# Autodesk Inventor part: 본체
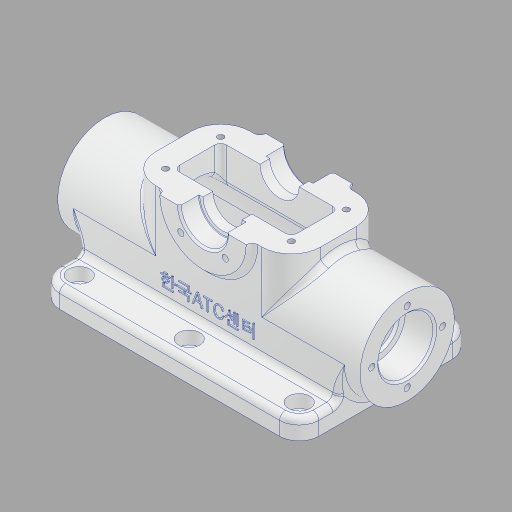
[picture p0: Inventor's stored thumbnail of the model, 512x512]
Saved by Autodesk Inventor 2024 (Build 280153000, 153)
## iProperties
Created: 2024-06
Part Number: 본체
Material: 알루미늄 6061
Document SubType Name: Modeling
Designer: kh_501
Density: 2.7 g/cm^3
Appearance: 알루미늄 - 평지
Mass: 551.84 g
Surface Area: 612.281 cm^2
Volume: 204.385 cm^3
Author: kh_501
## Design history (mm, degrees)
sketch "스케치1"
  geometry: L1 (66, 44)-(-66, 44); L2 (-66, 44)-(-66, -44); L3 (-66, -44)-(66, -44); L4 (66, -44)-(66, 44); L5 (66, 44)-(-66, -44); L6 (-66, 44)-(66, -44); 1 further point
  constraints: 12 end point, 2 midpoint, 2 parallel, 1 horizontal, 1 perpendicular
  dimensions: "d0" = 132 distance of L1.start L1.end; "d1" = 88 distance of L1.end L2.end
extrude "돌출1" new body sketch "스케치1" distance "d2" = 10; taper "d3" = 0 deg
sketch "스케치2"
  geometry: L1 (-77, 52)-(77, 52); L2 (77, 52)-(77, 28); L3 (77, 28)-(-77, 28); L4 (-77, 28)-(-77, 52); L5 (66, 0)-(-66, 0) reference; 2 further points
  constraints: 8 end point, 2 parallel, 1 horizontal, 1 midpoint, 1 perpendicular, 1 vertical alignment
  dimensions: "d4" = 48 diameter of L1 L3; "d5" = 28 distance from line of L5 L3.end; "d6" = 154 distance of L1.end L1.start
revolve "회전1" sketch "스케치2" stored, may be unused: angle "d7" = 90 deg
node "작업 평면1"
sketch "스케치4"
  geometry: L1 (-42, 24)-(42, 24); L2 (42, 24)-(42, -24); L3 (42, -24)-(-42, -24); L4 (-42, -24)-(-42, 24); L5 (-42, 24)-(42, -24); L6 (42, 24)-(-42, -24); 1 further point
  constraints: 12 end point, 2 midpoint, 2 parallel, 1 horizontal, 1 perpendicular
  dimensions: "d9" = 84 distance of L2.end L3.end; "d10" = 48 distance of L3.end L1.start
extrude "돌출2" join sketch "스케치4" stored distance "d11" = 10; taper "d12" = 0 deg
sketch "스케치8"
  geometry: L1 (84, -31)-(0, -31) reference; L2 (-24, -59)-(108, -59) reference; L3 (0, 0)-(84, 0) reference; C1 r 22 at (42, 0); 4 further points
  constraints: 1 centre point, 1 midpoint, 1 vertical alignment
  dimensions: "d19" = 44 diameter of C1; "d20" = 59 distance from line of L2 C1.centre
extrude "돌출4" join sketch "스케치8" distance "d21" = 3; taper "d22" = 0 deg
sketch "스케치9"
  geometry: L1 (88, 10)-(59.875, 10) reference; L2 (88, 0)-(88, 10) reference; L3 (88, 0)-(0, 0) reference; L4 (0, 0)-(0, 10) reference; L5 (28.125, 10)-(0, 10) reference; L6 (20, 28)-(20, 9.172); L7 (68, 28)-(68, 9.172); A1 r 24 centre (44, 28) between (28.125, 10) and (59.875, 10) reference; A2 r 24 centre (44, 28) between (20, 28) and (68, 28) reference; 5 further points
  constraints: 4 end point, 2 point on circle, 2 tangent, 2 vertical
extrude "돌출5" join sketch "스케치9" distance "d23" = 132; taper "d24" = 0 deg
sketch "스케치5"
  geometry: L1 (28, 0)-(-63.528, 0); L2 (28, -18)-(-63.528, -18); L3 (-63.528, 18)-(28, 18); L4 (0, 44)-(0, -44) reference; C1 r 24 at (28, 0) reference; A1 r 18 centre (28, 0) between (28, -18) and (28, 18); A2 r 18 centre (-63.528, 0) between (-63.528, 18) and (-63.528, -18); 5 further points
  constraints: 8 end point, 4 point on circle, 4 tangent, 2 centre point, 2 midpoint, 1 horizontal, 1 horizontal alignment, 1 parallel
  dimensions: "d15" = 28 distance from line of L4 L1.start; "d16" = 6 radial gap between concentric circles of C1 A1
extrude "돌출3" cut sketch "스케치5" stored distance "d17" = 120; taper "d18" = 0 deg
sketch "스케치10"
  geometry: L1 (-30, -12)-(30, -12); L2 (30, -12)-(30, 12); L3 (30, 12)-(-30, 12); L4 (-30, 12)-(-30, -12); L5 (-30, -12)-(30, 12); L6 (30, -12)-(-30, 12); 1 further point
  constraints: 12 end point, 2 midpoint, 2 parallel, 1 horizontal, 1 perpendicular
  dimensions: "d25" = 60 distance of L2.end L3.end; "d26" = 24 distance of L1.end L2.end
extrude "돌출6" cut sketch "스케치10" stored distance "d27" = 132; taper "d28" = 0 deg
sketch "스케치11"
  geometry: A1 r 22 centre (42, 0) between (20, 0) and (64, 0) reference; 2 further points
  constraints: 1 coincident
hole "구멍1" sketch "스케치11" at (42, 0) diameter "d29" = 20; stored, may be unused: countersink angle "d33" = 90 deg, drill point angle "d35" = 0 deg; dims "d30" = 6, "d31" = 24, "d32" = 10, "d34" = 8
sketch "스케치12"
  geometry: A1 r 22 centre (0, 0) between (-22, 0) and (22, 0) reference; 2 further points
  constraints: 1 coincident
hole "구멍2" sketch "스케치12" at (0, 0) diameter "d36" = 20; stored, may be unused: countersink angle "d40" = 90 deg, drill point angle "d42" = 0 deg; dims "d37" = 6, "d38" = 24, "d39" = 10, "d41" = 8
sketch "스케치13"
  geometry: C1 r 24 at (0, 0) reference; 2 further points
  constraints: 1 coincident
hole "구멍3" sketch "스케치13" at (0, 0) diameter "d43" = 22; stored, may be unused: countersink angle "d47" = 90 deg, drill point angle "d49" = 0 deg; dims "d44" = 6, "d45" = 28, "d46" = 15, "d48" = 8
sketch "스케치14"
  geometry: C1 r 24 at (0, 0) reference; 2 further points
  constraints: 1 coincident
hole "구멍4" sketch "스케치14" at (0, 0) diameter "d50" = 22; stored, may be unused: countersink angle "d54" = 90 deg, drill point angle "d56" = 0 deg; dims "d51" = 6, "d52" = 28, "d53" = 15, "d55" = 8
sketch "스케치15" dims "d57" = 36
  geometry: L1 (0, 0)-(0, 18); C1 r 14 at (0, 0) reference; C2 r 24 at (0, 0) reference; 2 further points
  constraints: 2 coincident, 2 end point, 1 vertical, 1 vertical alignment, 2 other
hole "구멍5" sketch "스케치15" at (0, 18) diameter "d58" = 3.242; stored, may be unused: countersink angle "d62" = 90 deg, drill point angle "d64" = 118 deg; dims "d59" = 8, "d60" = 28, "d61" = 15, "d63" = 10
sketch "스케치16"
  geometry: L1 (-32, -14)-(32, -14); L2 (32, -14)-(32, 14); L3 (32, 14)-(-32, 14); L4 (-32, 14)-(-32, -14); L5 (-32, -14)-(32, 14); L6 (32, -14)-(-32, 14); 5 further points
  constraints: 12 end point, 4 coincident, 2 midpoint, 2 parallel, 1 horizontal, 1 perpendicular
  dimensions: "d68" = 64 distance of L2.end L3.end; "d69" = 28 distance of L1.end L2.end
hole "구멍6" sketch "스케치16" at (-32, 14), (-32, -14), (32, -14), (32, 14) diameter "d70" = 3.242; stored, may be unused: countersink angle "d74" = 90 deg, drill point angle "d76" = 118 deg; dims "d71" = 8, "d72" = 4, "d73" = 2, "d75" = 10
sketch "스케치17" dims "d77" = 32
  geometry: L1 (42, 0)-(30.686, -11.314); L2 (42, 0)-(42, 13.322); A1 r 12 centre (42, 0) between (30, 0) and (54, 0) reference; 2 further points
  constraints: 4 end point, 2 coincident, 1 vertical, 3 other
  dimensions: "d78" = 45 deg angle of L1 L2
hole "구멍7" sketch "스케치17" at (30.686, -11.314) diameter "d79" = 3.242; stored, may be unused: countersink angle "d83" = 90 deg, drill point angle "d85" = 118 deg; dims "d80" = 8, "d81" = 4, "d82" = 2, "d84" = 10
fillet "모깎기1" dims "d89" = 10
sketch "스케치18"
  geometry: L1 (-56, -34)-(56, -34); L2 (56, -34)-(56, 34); L3 (56, 34)-(-56, 34); L4 (-56, 34)-(-56, -34); L5 (-56, -34)-(56, 34); L6 (56, -34)-(-56, 34); 7 further points
  constraints: 12 end point, 4 coincident, 4 midpoint, 2 parallel, 1 horizontal, 1 perpendicular
  dimensions: "d90" = 112 distance of L2.end L3.end; "d91" = 68 distance of L1.end L2.end
hole "구멍8" sketch "스케치18" at (-56, 34), (-56, -34), (0, -34), (0, 34), (56, 34), (56, -34) diameter "d92" = 6.6; stored, may be unused: countersink angle "d96" = 90 deg, drill point angle "d98" = 118 deg; dims "d93" = 8, "d94" = 11, "d95" = 6.6, "d97" = 10
sketch "스케치19"
  geometry: L1 (10, -10)-(122, -10) reference; 3 further points
  constraints: 1 midpoint, 1 vertical alignment, 1 other
  dimensions: "d99" = 20 distance from line of L1 point (66, 10)
feature "엠보싱1" sketch "스케치19" dims "d100" = 0.5, "d101" = 0
fillet "모깎기2" dims "d102" = 3
fillet "모깎기3" dims "d103" = 3
fillet "모깎기4" dims "d104" = 3
fillet "모깎기5" dims "d105" = 15
fillet "모깎기6" dims "d106" = 3
fillet "모깎기7" dims "d107" = 3
fillet "모깎기8" dims "d108" = 3
chamfer "모따기1" distance "d109" = 1; stored, may be unused: second distance "d110" = 2, angle "d111" = 45 deg
fillet "모깎기9" dims "d112" = 3
fillet "모깎기10" dims "d113" = 0.3
node "솔리드1"
mirror "미러1"
pattern_circular "원형 패턴1" dims angle "d66" = 360 deg
mirror "미러2"
pattern_circular "원형 패턴2" dims angle "d87" = 90 deg
mirror "미러3"
node "투영된 루프2"
node "투영된 루프3"
node "투영된 루프4"
feature "A9D066F2-1C7D-4E18-AEED-F7BC21143FA4" dims "d43" = 22, "d44" = 6, "d45" = 28, "d46" = 15, "d47" = 90 deg, "d48" = 8, "d49" = 0
other parameters: "d8" = -59
